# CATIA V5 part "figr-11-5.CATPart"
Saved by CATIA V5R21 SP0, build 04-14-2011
Part number: Part4
Bounding box of the stored display mesh (mm): x -40 to 40, y -90 to 150, z -30.056 to 96
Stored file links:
  D:\CATIA V5R21 E-RESOURCES\CATIA-V5R21\catia-v5r21-prt\c11-catia-v5r21-prt\c11-catia-v5r21-figr-11-5.CATPart
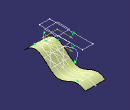
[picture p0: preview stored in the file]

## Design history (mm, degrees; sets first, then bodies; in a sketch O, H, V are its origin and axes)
Body1 (main body)
  Sketch1 on yz-plane, origin (0, 0, 0), H (0, 1, 0), V (0, 0, 1)
    spline S1 through (-90, 0) (-30, 20) (50, -30) (110, -10) (150, -20)
  Extrude1: Lim1 40, Lim2 40, Element1 Sketch1
  Plane1: type Offset, RefPlane xy-plane, Offset 50
  Sketch2 on Plane1, origin (0, 0, 50), H (1, 0, 0), V (0, 1, 0)
    spline S1 through (30, 100) (-10, 40) (20, -10) (-10, -60)
  Plane2: type Offset, RefPlane Plane1, Offset 46
  Sketch3 on Plane2, origin (0, 0, 96), H (1, 0, 0), V (0, 1, 0)
    line L1 (-20, 120) -> (20, 120)
    line L2 (20, 120) -> (20, -50)
    line L3 (20, -50) -> (-20, -50)
    line L4 (-20, -50) -> (-20, 120)
    horizontal: L1 H, L3 H
    vertical: L2 V, L4 V
  MultiSel1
